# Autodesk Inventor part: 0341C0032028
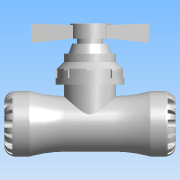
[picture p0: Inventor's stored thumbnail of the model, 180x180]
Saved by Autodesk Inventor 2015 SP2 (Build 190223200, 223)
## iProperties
Created: 2016-12
Part Number: 0341C0032028
Material: PVC-Piping
Description: PLASSON COPPER PIPE ADAPTOR STOPTAP 32-28 SERIES 1
Document SubType Name: Modeling
Designer: KIM
Mass: 61.7504 g
Surface Area: 140.097 cm^2
Volume: 44.1074 cm^3
Density: 1.4 g/cm^3
Appearance: Smooth - White
Author: KIM
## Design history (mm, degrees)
derived "0341C.ipt"
feature "Solid1::0341C.ipt"
feature "Solid2::0341C.ipt"
tag "TaggingFeature1"
body "Solid1"
other parameters: "d1" = 22.68, "d2" = 32, "d4" = 58, "d6" = 54, "d8" = 49.3, "d13" = 7.2, "d14" = 7.2, "d15" = 0, "d17" = 360 deg, "d19" = 8 deg, "d20" = 0.64, "d21" = 0.64, "d22" = 8 deg, "d24" = 0, "d26" = 360 deg, "d33" = 5.8, "d35" = 4, "d65" = 0.58, "d69" = 152, "d71" = 28, "d72" = 58, "d74" = 22.68, "d75" = 76, "d76" = 3.5, "d77" = 54, "d80" = 7.2, "d82" = 7.2, "d83" = 0, "d85" = 360 deg, "d87" = 0.56, "d88" = 8 deg, "d89" = 8 deg, "d90" = 0.56, "d92" = 0, "d94" = 360 deg, "d96" = 89, "d97" = 58, "d98" = 46.4, "d99" = 34.8, "d100" = 135 deg, "d101" = 23.2, "d102" = 70 deg, "d103" = 48.95, "d104" = 71.2, "d105" = 62.3, "d107" = 75.65, "d108" = 104.4, "d110" = 12.015, "d111" = 4.005, "d112" = 17.4, "d113" = 0, "d114" = 60.9, "d115" = 5.8, "d116" = 0, "d117" = 5.8, "d119" = 0, "d121" = 360 deg, "d127" = 0, "d128" = 0.58, "d_" = 32, "E_" = 58, "H_" = 152, "l_" = 54, "A_" = 89, "l_1" = 54, "d_1" = 28, "E_1" = 58, "d9" = 9, "d11" = 58, "d78" = 58, "d81" = 9, "d109" = 13.35
